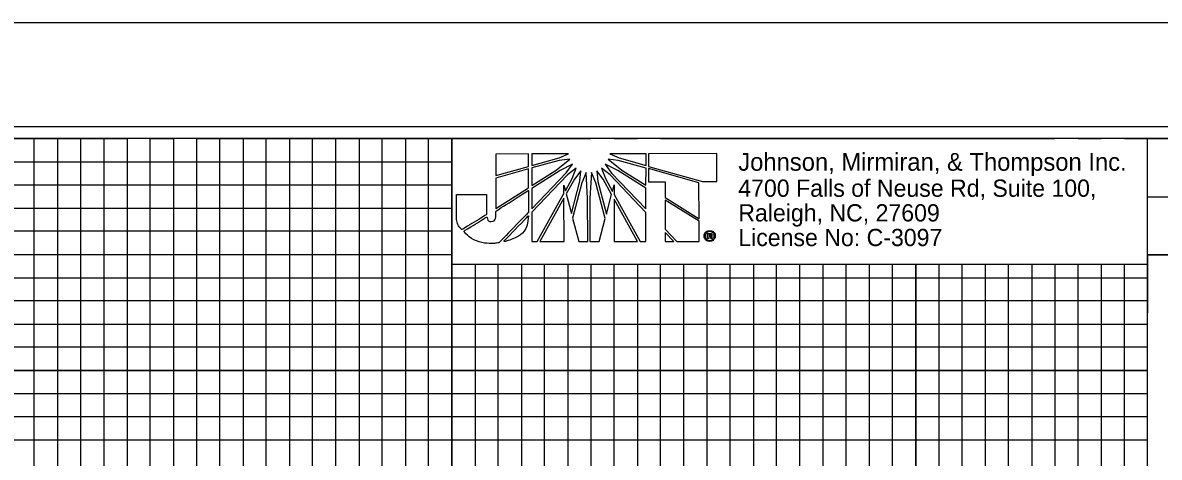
# Model space of a CAD drawing. Extents: x 1648862 to 1650739, y 844691 to 845791.
# Drawn here: x 1650086.8 to 1650331.8, y 845697.3 to 845791 of the extents above; entities that cross this region are included whole.
import ezdxf

# ---------------------------------------------------------------- set-up
doc = ezdxf.new("R2010")
doc.units = 0
for name, color, linetype in [('Prop 8 AWG with gnd feeder circuit', 7, 'Continuous'), ('Prop Berm Ditch Text', 7, 'Continuous'), ('Prop Conc Barrier Transition Section', 7, 'Continuous'), ('Prop Conc Expressway Gutter', 7, 'Continuous'), ('Prop DGN Element Guardrail', 7, 'Continuous'), ('Prop Dimension', 7, 'Continuous'), ('Prop Dimension Text', 7, 'Continuous'), ('Prop Easement Construction', 7, 'Continuous'), ('Prop Easement Construction Station Offsets', 7, 'Continuous')]:
    doc.layers.add(name, color=color, linetype=linetype)

msp = doc.modelspace()

# ---------------------------------------------------------------- linework, layer by layer
at = {"layer": 'Prop 8 AWG with gnd feeder circuit'}
for p, q in [((1650195.79, 845762.71), (1650188.77, 845762.7)), ((1650188.77, 845762.7), (1650188.77, 845758.05)), ((1650195.79, 845760), (1650195.79, 845762.71)), ((1650204.41, 845762.75), (1650196.52, 845762.75)), ((1650196.52, 845762.75), (1650196.52, 845760.23)), ((1650202.4, 845761.86), (1650204.41, 845762.75)), ((1650221.14, 845762.73), (1650213.35, 845762.76)), ((1650213.35, 845762.76), (1650215.32, 845761.84)), ((1650221.14, 845760.21), (1650221.14, 845762.73)), ((1650236.43, 845762.78), (1650221.68, 845762.77)), ((1650221.68, 845762.77), (1650221.68, 845760.06)), ((1650236.44, 845756.74), (1650236.43, 845762.78)), ((1650188.77, 845758.05), (1650195.79, 845760)), ((1650196.52, 845760.23), (1650202.4, 845761.86)), ((1650202.4, 845761.31), (1650196.52, 845759.69)), ((1650196.52, 845759.69), (1650196.52, 845755.89)), ((1650201.79, 845759.23), (1650204.69, 845761.59)), ((1650204.69, 845761.59), (1650202.4, 845761.31)), ((1650205.27, 845760.51), (1650202.6, 845759.15)), ((1650203.92, 845758.61), (1650205.27, 845760.51)), ((1650206.08, 845759.66), (1650204.22, 845758.22)), ((1650205.23, 845757.42), (1650206.08, 845759.66)), ((1650211.53, 845759.67), (1650212.39, 845757.42)), ((1650213.39, 845758.23), (1650211.53, 845759.67)), ((1650212.35, 845760.51), (1650213.71, 845758.58)), ((1650215.06, 845759.16), (1650212.35, 845760.51)), ((1650212.96, 845761.6), (1650215.9, 845759.2)), ((1650215.13, 845761.33), (1650212.96, 845761.6)), ((1650221.14, 845759.68), (1650215.13, 845761.33)), ((1650215.32, 845761.84), (1650221.14, 845760.21)), ((1650221.1, 845755.96), (1650221.14, 845759.68)), ((1650221.68, 845760.06), (1650221.68, 845759.98)), ((1650221.68, 845759.98), (1650233.3, 845756.74)), ((1650195.79, 845759.49), (1650188.77, 845757.52)), ((1650188.77, 845757.52), (1650188.78, 845750.97)), ((1650195.79, 845755.43), (1650195.79, 845759.49)), ((1650196.52, 845755.89), (1650201.79, 845759.23)), ((1650202.6, 845759.15), (1650196.52, 845755.28)), ((1650196.53, 845750.9), (1650203.92, 845758.61)), ((1650204.22, 845758.22), (1650196.53, 845750.16)), ((1650203.76, 845754.74), (1650205.23, 845757.42)), ((1650205.7, 845757.25), (1650203.96, 845754.08)), ((1650207.09, 845759.04), (1650205.7, 845757.25)), ((1650206.9, 845756.87), (1650207.09, 845759.04)), ((1650208.25, 845758.73), (1650207.29, 845756.48)), ((1650208.56, 845753.19), (1650208.25, 845758.73)), ((1650209.41, 845758.73), (1650209.05, 845753.19)), ((1650210.34, 845756.48), (1650209.41, 845758.73)), ((1650210.53, 845759.04), (1650210.77, 845756.8)), ((1650211.89, 845757.26), (1650210.53, 845759.04)), ((1650213.71, 845753.97), (1650211.89, 845757.26)), ((1650212.39, 845757.42), (1650213.89, 845754.63)), ((1650221.1, 845750.11), (1650213.39, 845758.23)), ((1650213.71, 845758.58), (1650221.1, 845750.84)), ((1650221.1, 845755.33), (1650215.06, 845759.16)), ((1650215.9, 845759.2), (1650221.1, 845755.96)), ((1650221.68, 845759.56), (1650221.68, 845759.52)), ((1650232.56, 845756.47), (1650221.68, 845759.56)), ((1650221.68, 845759.52), (1650221.69, 845756.69)), ((1650188.78, 845750.97), (1650195.79, 845755.43)), ((1650196.52, 845755.28), (1650196.53, 845750.9)), ((1650203.41, 845754.16), (1650203.41, 845756.01)), ((1650203.41, 845756.01), (1650203.76, 845754.74)), ((1650205.09, 845749.87), (1650206.9, 845756.87)), ((1650207.29, 845756.48), (1650205.32, 845748.89)), ((1650212.36, 845748.78), (1650210.34, 845756.48)), ((1650210.77, 845756.8), (1650212.59, 845749.71)), ((1650213.89, 845754.63), (1650214.25, 845756.02)), ((1650214.25, 845756.02), (1650214.25, 845753.97)), ((1650221.1, 845750.84), (1650221.1, 845755.33)), ((1650221.69, 845756.69), (1650225.29, 845756.69)), ((1650225.29, 845756.69), (1650225.29, 845753.32)), ((1650232.57, 845748.72), (1650232.56, 845756.47)), ((1650233.3, 845756.74), (1650236.44, 845756.74)), ((1650197.69, 845743.79), (1650203.41, 845754.16)), ((1650203.42, 845753.15), (1650198.24, 845743.79)), ((1650203.47, 845743.8), (1650203.42, 845753.15)), ((1650203.96, 845754.08), (1650205.09, 845749.87)), ((1650208.57, 845743.84), (1650208.56, 845753.19)), ((1650209.05, 845753.19), (1650209.06, 845743.84)), ((1650212.59, 845749.71), (1650213.71, 845753.97)), ((1650214.25, 845753.97), (1650219.87, 845743.81)), ((1650219.29, 845743.85), (1650214.25, 845752.97)), ((1650214.25, 845752.97), (1650214.26, 845743.84)), ((1650225.29, 845753.32), (1650232.57, 845748.72)), ((1650225.29, 845752.74), (1650225.3, 845746.47)), ((1650232.57, 845748.18), (1650225.29, 845752.74)), ((1650196.53, 845750.16), (1650196.53, 845743.79)), ((1650221.11, 845743.81), (1650221.1, 845750.11)), ((1650205.32, 845748.89), (1650206.64, 845743.83)), ((1650211.01, 845743.84), (1650212.36, 845748.78)), ((1650232.57, 845743.82), (1650232.57, 845748.18)), ((1650225.3, 845746.47), (1650227.81, 845743.82)), ((1650227.12, 845743.82), (1650225.3, 845745.78)), ((1650225.3, 845745.78), (1650225.3, 845743.82)), ((1650234.42, 845744.49), (1650234.42, 845745.56)), ((1650234.42, 845745.56), (1650234.86, 845745.56)), ((1650234.86, 845745.36), (1650234.66, 845745.36)), ((1650234.66, 845745.36), (1650234.66, 845745.1)), ((1650234.66, 845745.1), (1650234.86, 845745.1)), ((1650234.86, 845744.91), (1650234.66, 845744.91)), ((1650234.66, 845744.91), (1650234.66, 845744.49)), ((1650234.86, 845746.19), (1650234.86, 845745.97)), ((1650234.86, 845745.97), (1650234.86, 845746.19)), ((1650234.86, 845745.56), (1650234.86, 845745.36)), ((1650234.86, 845745.36), (1650234.86, 845745.56)), ((1650234.86, 845745.56), (1650234.92, 845745.56)), ((1650234.89, 845745.36), (1650234.86, 845745.36)), ((1650234.86, 845745.1), (1650234.86, 845744.91)), ((1650234.86, 845744.91), (1650234.86, 845745.1)), ((1650234.86, 845745.1), (1650234.87, 845745.1)), ((1650234.87, 845744.91), (1650234.86, 845744.91)), ((1650196.53, 845743.79), (1650197.69, 845743.79)), ((1650198.24, 845743.79), (1650203.47, 845743.8)), ((1650206.64, 845743.83), (1650208.57, 845743.84)), ((1650209.06, 845743.84), (1650211.01, 845743.84)), ((1650214.26, 845743.84), (1650219.29, 845743.85)), ((1650219.87, 845743.81), (1650221.11, 845743.81)), ((1650225.3, 845743.82), (1650227.12, 845743.82)), ((1650227.81, 845743.82), (1650232.57, 845743.82)), ((1650234.66, 845744.49), (1650234.42, 845744.49)), ((1650234.86, 845744.07), (1650234.86, 845743.83)), ((1650234.86, 845743.83), (1650234.86, 845744.07)), ((1650234.86, 845744.07), (1650234.87, 845744.07)), ((1650234.87, 845743.83), (1650234.86, 845743.83))]:
    msp.add_line(p, q, dxfattribs=at)
msp.add_lwpolyline([(1650179.28, 845738.96), (1650329.23, 845738.96), (1650329.23, 845766.02), (1650179.28, 845766.02)], close=True, dxfattribs=at)
for points in [[(1650188.77, 845758.05), (1650195.79, 845760), (1650195.79, 845762.71), (1650188.77, 845762.7), (1650188.77, 845758.05)], [(1650202.4, 845761.86), (1650204.41, 845762.75), (1650196.52, 845762.75), (1650196.52, 845760.23), (1650202.4, 845761.86)], [(1650215.32, 845761.84), (1650221.14, 845760.21), (1650221.14, 845762.73), (1650213.35, 845762.76), (1650215.32, 845761.84)], [(1650236.43, 845762.78), (1650221.68, 845762.77), (1650221.68, 845760.06), (1650221.68, 845759.98), (1650233.3, 845756.74), (1650236.44, 845756.74), (1650236.43, 845762.78)], [(1650196.52, 845759.69), (1650196.52, 845755.89), (1650201.79, 845759.23), (1650204.69, 845761.59), (1650202.4, 845761.31), (1650196.52, 845759.69)], [(1650196.52, 845755.28), (1650196.53, 845750.9), (1650203.92, 845758.61), (1650205.27, 845760.51), (1650202.6, 845759.15), (1650196.52, 845755.28)], [(1650206.08, 845759.66), (1650204.22, 845758.22), (1650196.53, 845750.16), (1650196.53, 845743.79), (1650197.69, 845743.79), (1650203.41, 845754.16), (1650203.41, 845756.01), (1650203.76, 845754.74), (1650205.23, 845757.42), (1650206.08, 845759.66)], [(1650211.53, 845759.67), (1650212.39, 845757.42), (1650213.89, 845754.63), (1650214.25, 845756.02), (1650214.25, 845753.97), (1650219.87, 845743.81), (1650221.11, 845743.81), (1650221.1, 845750.11), (1650213.39, 845758.23), (1650211.53, 845759.67)], [(1650212.35, 845760.51), (1650213.71, 845758.58), (1650221.1, 845750.84), (1650221.1, 845755.33), (1650215.06, 845759.16), (1650212.35, 845760.51)], [(1650212.96, 845761.6), (1650215.9, 845759.2), (1650221.1, 845755.96), (1650221.14, 845759.68), (1650215.13, 845761.33), (1650212.96, 845761.6)], [(1650188.78, 845750.97), (1650195.79, 845755.43), (1650195.79, 845759.49), (1650188.77, 845757.52), (1650188.78, 845750.97)], [(1650207.09, 845759.04), (1650205.7, 845757.25), (1650203.96, 845754.08), (1650205.09, 845749.87), (1650206.9, 845756.87), (1650207.09, 845759.04)], [(1650207.29, 845756.48), (1650205.32, 845748.89), (1650206.64, 845743.83), (1650208.57, 845743.84), (1650208.56, 845753.19), (1650208.25, 845758.73), (1650207.29, 845756.48)], [(1650209.41, 845758.73), (1650209.05, 845753.19), (1650209.06, 845743.84), (1650211.01, 845743.84), (1650212.36, 845748.78), (1650210.34, 845756.48), (1650209.41, 845758.73)], [(1650210.53, 845759.04), (1650210.77, 845756.8), (1650212.59, 845749.71), (1650213.71, 845753.97), (1650211.89, 845757.26), (1650210.53, 845759.04)], [(1650221.68, 845759.56), (1650221.68, 845759.52), (1650221.69, 845756.69), (1650225.29, 845756.69), (1650225.29, 845753.32), (1650232.57, 845748.72), (1650232.56, 845756.47), (1650221.68, 845759.56)], [(1650198.24, 845743.79), (1650203.47, 845743.8), (1650203.42, 845753.15), (1650198.24, 845743.79)], [(1650214.26, 845743.84), (1650219.29, 845743.85), (1650214.25, 845752.97), (1650214.26, 845743.84)], [(1650225.29, 845752.74), (1650225.3, 845746.47), (1650227.81, 845743.82), (1650232.57, 845743.82), (1650232.57, 845748.18), (1650225.29, 845752.74), (1650225.29, 845752.74)], [(1650225.3, 845743.82), (1650225.3, 845743.82), (1650227.12, 845743.82), (1650225.3, 845745.78), (1650225.3, 845743.82)], [(1650235.33, 845744.74), (1650235.33, 845744.68), (1650235.33, 845744.64), (1650235.33, 845744.61), (1650235.36, 845744.49), (1650235.14, 845744.49)]]:
    msp.add_lwpolyline(points, dxfattribs=at)
for points, degree in [([(1650187.78, 845748.13), (1650187.36, 845748.13), (1650187, 845748.37), (1650186.85, 845749.14), (1650186.85, 845749.14), (1650181.81, 845746.02), (1650181.81, 845746.02), (1650183.37, 845744.39), (1650185.85, 845743.42), (1650187.94, 845743.42), (1650188.49, 845743.42), (1650188.9, 845743.47), (1650189.48, 845743.59), (1650189.48, 845743.59), (1650195.8, 845750.12), (1650195.8, 845750.12), (1650195.8, 845750.12), (1650195.79, 845754.85), (1650195.79, 845754.85), (1650195.79, 845754.85), (1650188.78, 845750.38), (1650188.78, 845750.38), (1650188.78, 845748.61), (1650188.35, 845748.14), (1650187.78, 845748.13)], 3), ([(1650187.78, 845748.13), (1650187.36, 845748.13), (1650187, 845748.37), (1650186.85, 845749.14), (1650186.85, 845749.14), (1650181.81, 845746.02), (1650181.81, 845746.02), (1650183.37, 845744.39), (1650185.85, 845743.42), (1650187.94, 845743.42), (1650188.49, 845743.42), (1650188.9, 845743.47), (1650189.48, 845743.59), (1650189.48, 845743.59), (1650195.8, 845750.12), (1650195.8, 845750.12), (1650195.8, 845750.12), (1650195.79, 845754.85), (1650195.79, 845754.85), (1650195.79, 845754.85), (1650188.78, 845750.38), (1650188.78, 845750.38), (1650188.78, 845748.61), (1650188.35, 845748.14), (1650187.78, 845748.13)], 3), ([(1650186.76, 845753.98), (1650186.76, 845753.98), (1650180.27, 845753.98), (1650180.27, 845753.98), (1650180.27, 845753.98), (1650180.27, 845749.91), (1650180.27, 845749.91), (1650180.27, 845749.91), (1650180.27, 845749.48), (1650180.27, 845749.48), (1650180.27, 845748.21), (1650180.69, 845747.2), (1650181.43, 845746.36), (1650181.43, 845746.36), (1650186.77, 845749.6), (1650186.77, 845749.69), (1650186.77, 845749.69), (1650186.76, 845753.98), (1650186.76, 845753.98)], 3), ([(1650195.8, 845749.38), (1650195.8, 845749.38), (1650190.34, 845743.74), (1650190.34, 845743.74), (1650193.01, 845744.4), (1650195.68, 845746.17), (1650195.8, 845749.38)], 3), ([(1650234.86, 845743.83), (1650234.54, 845743.83), (1650234.25, 845743.95), (1650234.02, 845744.18), (1650233.78, 845744.41), (1650233.67, 845744.69), (1650233.67, 845745.02), (1650233.67, 845745.35), (1650233.78, 845745.64), (1650234.02, 845745.85), (1650234.25, 845746.08), (1650234.52, 845746.19), (1650234.86, 845746.19)], 3), ([(1650234.86, 845745.97), (1650234.59, 845745.97), (1650234.37, 845745.88), (1650234.18, 845745.71), (1650234, 845745.52), (1650233.9, 845745.29), (1650233.9, 845745.02), (1650233.9, 845744.76), (1650234, 845744.53), (1650234.18, 845744.34), (1650234.37, 845744.16), (1650234.59, 845744.07), (1650234.86, 845744.07)], 3), ([(1650234.86, 845746.19), (1650235.19, 845746.19), (1650235.47, 845746.08), (1650235.7, 845745.85), (1650235.94, 845745.64), (1650236.06, 845745.36), (1650236.06, 845745.03)], 3), ([(1650234.87, 845744.07), (1650235.13, 845744.07), (1650235.35, 845744.16), (1650235.54, 845744.34), (1650235.72, 845744.53), (1650235.82, 845744.76), (1650235.82, 845745.03), (1650235.82, 845745.29), (1650235.72, 845745.52), (1650235.54, 845745.71), (1650235.35, 845745.88), (1650235.13, 845745.97), (1650234.86, 845745.97)], 3), ([(1650234.87, 845745.1), (1650235.02, 845745.1), (1650235.1, 845745.15), (1650235.1, 845745.24), (1650235.1, 845745.32), (1650235.03, 845745.36), (1650234.89, 845745.36)], 3), ([(1650236.06, 845745.03), (1650236.06, 845744.69), (1650235.94, 845744.41), (1650235.72, 845744.18), (1650235.48, 845743.95), (1650235.2, 845743.83), (1650234.87, 845743.83)], 3), ([(1650235.05, 845744.87), (1650235.02, 845744.89), (1650234.96, 845744.91), (1650234.87, 845744.91)], 2), ([(1650234.92, 845745.56), (1650235.2, 845745.56), (1650235.33, 845745.45), (1650235.33, 845745.24), (1650235.33, 845745.14), (1650235.3, 845745.06), (1650235.21, 845745)], 3), ([(1650235.21, 845745), (1650235.28, 845744.97), (1650235.32, 845744.88), (1650235.33, 845744.74)], 2), ([(1650235.14, 845744.49), (1650235.11, 845744.55), (1650235.09, 845744.61), (1650235.09, 845744.68), (1650235.09, 845744.78), (1650235.08, 845744.84), (1650235.05, 845744.87)], 3)]:
    msp.add_open_spline(points, degree=degree, dxfattribs=at)
at = {"layer": 'Prop Berm Ditch Text'}
msp.add_line((1650329.23, 845740.94), (1650329.23, 845728.45), dxfattribs=at)
at = {"layer": 'Prop Conc Barrier Transition Section'}
msp.add_lwpolyline([(1648862.28, 844691.02), (1650546.28, 844691.02), (1650546.28, 845791.02), (1648862.28, 845791.02)], close=True, dxfattribs=at)
at = {"layer": 'Prop Conc Expressway Gutter'}
for p, q in [((1649079.28, 845761.02), (1650179.28, 845761.02)), ((1650329.23, 845761.02), (1650329.28, 845761.02)), ((1650179.28, 845755.98), (1649079.28, 845755.67)), ((1650329.28, 845756.02), (1650329.23, 845756.02)), ((1649079.28, 845751.02), (1650179.28, 845751.02)), ((1650329.23, 845751.02), (1650329.28, 845751.02))]:
    msp.add_line(p, q, dxfattribs=at)
for points in [[(1650089.28, 845266.02), (1650089.28, 845766.02), (1650094.28, 845766.02), (1650094.28, 845266.02)], [(1650099.28, 845266.02), (1650099.28, 845766.02), (1650109.28, 845766.02), (1650109.28, 845266.02)], [(1650114.28, 845266.02), (1650114.28, 845766.02), (1650119.28, 845766.02), (1650119.28, 845266.02)], [(1650124.28, 845266.02), (1650124.28, 845766.02), (1650134.28, 845766.02), (1650134.28, 845266.02)], [(1650139.28, 845266.02), (1650139.28, 845766.02), (1650144.28, 845766.02), (1650144.28, 845266.02)], [(1650149.28, 845266.02), (1650149.28, 845766.02), (1650159.28, 845766.02), (1650159.28, 845266.02)], [(1650164.28, 845266.02), (1650164.28, 845766.02), (1650169.28, 845766.02), (1650169.28, 845266.02)], [(1650174.28, 845266.02), (1650174.28, 845766.02), (1650184.28, 845766.02)], [(1650189.28, 845766.02), (1650194.28, 845766.02)], [(1650199.28, 845766.02), (1650209.28, 845766.02)], [(1650214.28, 845766.02), (1650219.28, 845766.02)], [(1650224.28, 845766.02), (1650234.28, 845766.02)], [(1650239.28, 845766.02), (1650244.28, 845766.02)], [(1650249.28, 845766.02), (1650259.28, 845766.02)], [(1650264.28, 845766.02), (1650269.28, 845766.02)], [(1650274.28, 845766.02), (1650284.28, 845766.02)], [(1650289.28, 845766.02), (1650294.28, 845766.02)], [(1650299.28, 845766.02), (1650309.28, 845766.02)], [(1650314.28, 845766.02), (1650319.28, 845766.02)], [(1650324.28, 845766.02), (1650334.28, 845766.02)], [(1650179.28, 845746.02), (1649079.28, 845746.02), (1649079.28, 845736.02), (1650329.28, 845736.02)], [(1650329.28, 845746.02), (1650329.23, 845746.02)], [(1650184.28, 845738.96), (1650184.28, 845266.02), (1650189.28, 845266.02), (1650189.28, 845738.96)], [(1650194.28, 845738.96), (1650194.28, 845266.02), (1650199.28, 845266.02), (1650199.28, 845738.96)], [(1650209.28, 845738.96), (1650209.28, 845266.02), (1650214.28, 845266.02), (1650214.28, 845738.96)], [(1650219.28, 845266.02), (1650224.28, 845266.02), (1650224.28, 845738.96)], [(1650219.28, 845738.96), (1650219.28, 845266.02)], [(1650234.28, 845738.96), (1650234.28, 845266.02), (1650239.28, 845266.02), (1650239.28, 845738.96)], [(1650244.28, 845738.96), (1650244.28, 845266.02), (1650249.28, 845266.02), (1650249.28, 845738.96)], [(1650259.28, 845738.96), (1650259.28, 845266.02), (1650264.28, 845266.02), (1650264.28, 845738.96)], [(1650269.28, 845738.96), (1650269.28, 845266.02), (1650274.28, 845266.02), (1650274.28, 845738.96)], [(1650284.28, 845738.96), (1650284.28, 845266.02), (1650289.28, 845266.02), (1650289.28, 845738.96)], [(1650294.28, 845738.96), (1650294.28, 845266.02), (1650299.28, 845266.02), (1650299.28, 845738.96)], [(1650309.28, 845738.96), (1650309.28, 845266.02), (1650314.28, 845266.02), (1650314.28, 845738.96)], [(1650319.28, 845738.96), (1650319.28, 845266.02), (1650324.28, 845266.02), (1650324.28, 845738.96)], [(1650329.23, 845731.02), (1649079.28, 845731.02), (1649079.28, 845726.02), (1650329.28, 845726.02)], [(1650329.28, 845721.02), (1649079.28, 845721.02), (1649079.28, 845711.02), (1650329.28, 845711.02)], [(1650329.28, 845706.02), (1649079.28, 845706.02), (1649079.28, 845701.02), (1650329.28, 845701.02)]]:
    msp.add_lwpolyline(points, dxfattribs=at)
at = {"layer": 'Prop DGN Element Guardrail'}
msp.add_line((1650329.23, 845753.47), (1650529.28, 845753.47), dxfattribs=at)
for points in [[(1650529.28, 845766.02), (1649029.28, 845766.02), (1649029.28, 844716.02), (1650529.28, 844716.02)], [(1650329.23, 845766.02), (1650529.28, 845766.02), (1650529.28, 845740.97), (1650329.23, 845740.97)], [(1650329.23, 845740.97), (1650429.28, 845740.97), (1650429.28, 845628.47), (1650329.23, 845628.47)]]:
    msp.add_lwpolyline(points, close=True, dxfattribs=at)
at = {"layer": 'Prop Dimension'}
for points in [[(1649779.28, 845266.02), (1649829.28, 845266.02), (1649829.28, 845766.02), (1649879.28, 845766.02), (1649879.28, 845266.02), (1649929.28, 845266.02), (1649929.28, 845766.02), (1649979.28, 845766.02), (1649979.28, 845266.02), (1650029.28, 845266.02), (1650029.28, 845766.02), (1650079.28, 845766.02), (1650079.28, 845266.02), (1650129.28, 845266.02), (1650129.28, 845766.02), (1650179.28, 845766.02), (1650179.28, 845266.02), (1650229.28, 845266.02), (1650229.28, 845738.96)], [(1650229.28, 845766.02), (1650279.28, 845766.02)], [(1650279.28, 845738.96), (1650279.28, 845266.02), (1650329.28, 845266.02), (1650329.28, 845766.02), (1650355.58, 845766.02)], [(1649029.28, 845716.02), (1650329.28, 845716.02)]]:
    msp.add_lwpolyline(points, dxfattribs=at)
at = {"layer": 'Prop Dimension Text'}
msp.add_line((1649029.28, 845741.02), (1650179.28, 845741.02), dxfattribs=at)
for points in [[(1649804.28, 845266.02), (1649854.28, 845266.02), (1649854.28, 845766.02), (1649904.28, 845766.02), (1649904.28, 845266.02), (1649954.28, 845266.02), (1649954.28, 845766.02), (1650004.28, 845766.02), (1650004.28, 845266.02), (1650054.28, 845266.02), (1650054.28, 845766.02), (1650104.28, 845766.02), (1650104.28, 845266.02), (1650154.28, 845266.02), (1650154.28, 845766.02), (1650204.28, 845766.02)], [(1650254.28, 845766.02), (1650304.28, 845766.02)], [(1650204.28, 845738.96), (1650204.28, 845266.02), (1650254.28, 845266.02), (1650254.28, 845738.96)], [(1650304.28, 845738.96), (1650304.28, 845266.02), (1650354.28, 845266.02), (1650354.28, 845604.97)]]:
    msp.add_lwpolyline(points, dxfattribs=at)
at = {"layer": 'Prop Easement Construction'}
msp.add_lwpolyline([(1648875.28, 844713.47), (1650541.78, 844713.47), (1650541.78, 845768.57), (1648875.28, 845768.57)], close=True, dxfattribs=at)
at = {"layer": 'Prop Easement Construction Station Offsets'}
for p, q in [((1650129.28, 845266.02), (1650129.28, 845766.02)), ((1650179.28, 845266.02), (1650179.28, 845766.02)), ((1650229.28, 845266.02), (1650229.28, 845738.96)), ((1650279.28, 845266.02), (1650279.28, 845738.96)), ((1650329.23, 845716.02), (1649029.28, 845716.02))]:
    msp.add_line(p, q, dxfattribs=at)

# ---------------------------------------------------------------- texts
at = {"layer": 'Prop 8 AWG with gnd feeder circuit'}
for s, height, p in [('Johnson, Mirmiran, & Thompson Inc.', 3.8315, (1650241.03, 845759.09)), ('4700 Falls of Neuse Rd, Suite 100, ', 3.722, (1650241.03, 845753.47)), ('Raleigh, NC, 27609', 3.722, (1650241.03, 845748.15)), ('License No: C-3097', 3.722, (1650241.03, 845742.83))]:
    msp.add_text(s, height=height, rotation=360, dxfattribs=at).set_placement(p)

doc.saveas('drawing.dxf')
